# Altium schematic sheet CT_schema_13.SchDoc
size 254 x 194 mm
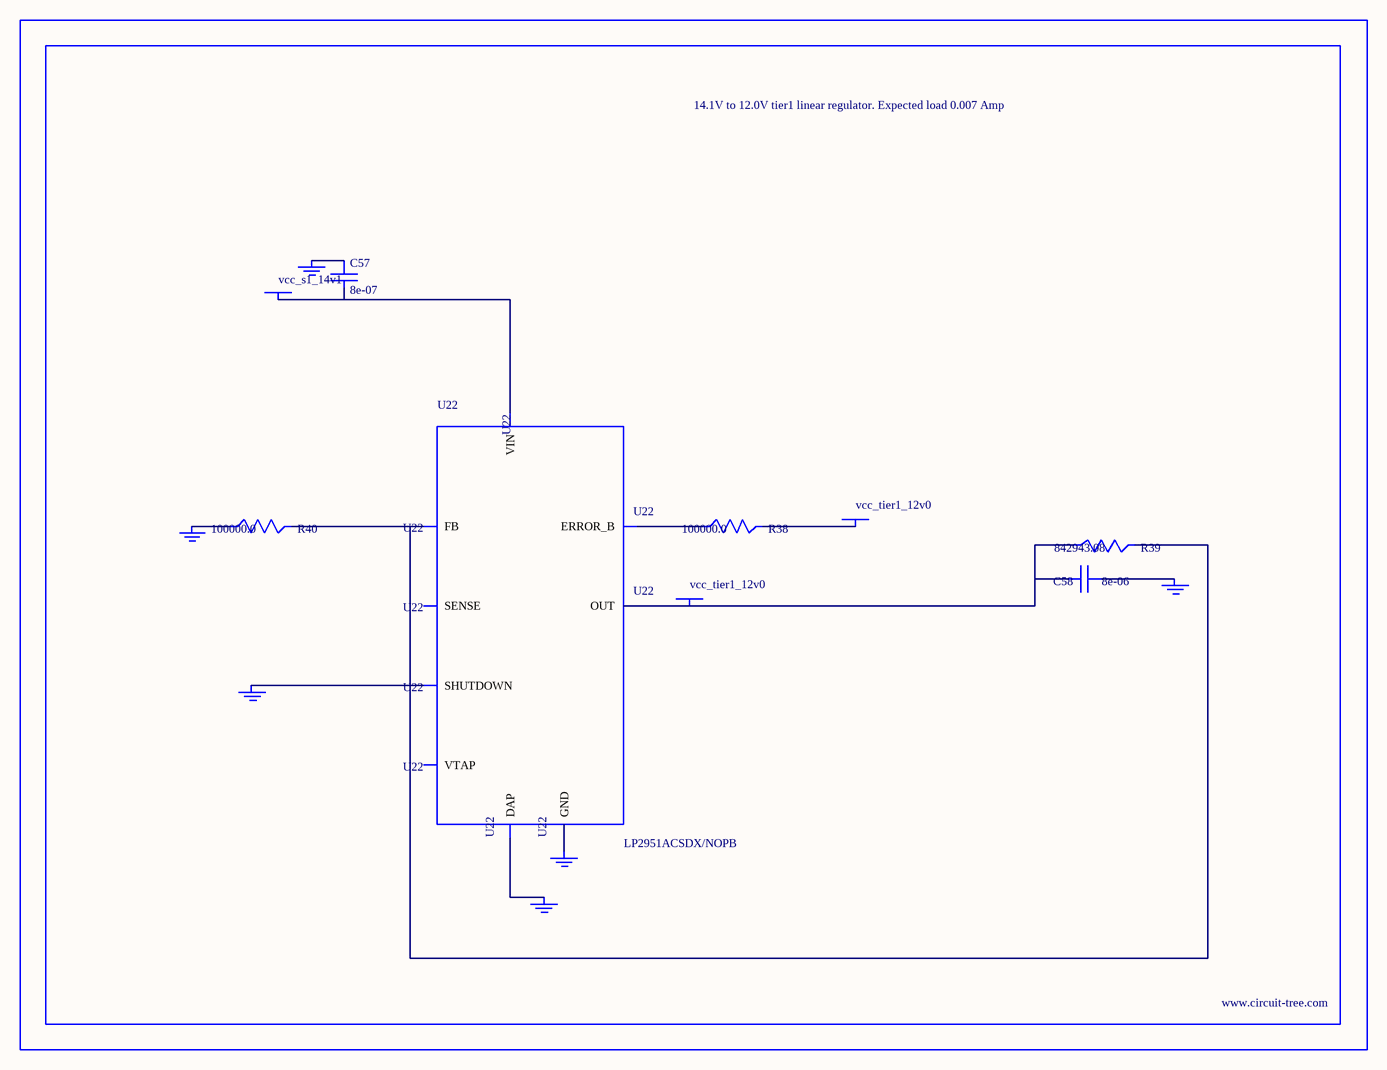
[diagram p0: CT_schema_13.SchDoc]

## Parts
BORDER12  (no value)
C57  8e-07  [R0603]
C58  8e-06  [R0603]
GND_INSTANCE_12_0  (no value)
GND_INSTANCE_12_1  (no value)
GND_INSTANCE_12_2  (no value)
GND_INSTANCE_12_3  (no value)
GND_INSTANCE_12_4  (no value)
GND_INSTANCE_12_5  (no value)
POWER_INSTANCE_12_0  vcc_tier1_12v0
POWER_INSTANCE_12_1  vcc_s1_14v1
POWER_INSTANCE_12_2  vcc_tier1_12v0
R38  100000.0  [R0603]
R39  842943.08  [R0603]
R40  100000.0  [R0603]
U22  LP2951ACSDX/NOPB  [WSON-8]

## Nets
NetC57_1: C57.1 GND_INSTANCE_12_3.0(GND)
NetC57_2: C57.2 POWER_INSTANCE_12_1.0(PWR) U22.8(VIN)
NetC58_1: C58.1 GND_INSTANCE_12_0.0(GND)
NetC58_2: C58.2 POWER_INSTANCE_12_2.0(PWR) R39.1 U22.1(OUT)
NetGND_INSTANCE_12_1_0: GND_INSTANCE_12_1.0(GND) U22.3(SHUTDOWN)
NetGND_INSTANCE_12_2_0: GND_INSTANCE_12_2.0(GND) R40.1
NetGND_INSTANCE_12_4_0: GND_INSTANCE_12_4.0(GND) U22.PAD(DAP)
NetGND_INSTANCE_12_5_0: GND_INSTANCE_12_5.0(GND) U22.4(GND)
NetPOWER_INSTANCE_12_0_0: POWER_INSTANCE_12_0.0(PWR) R38.2
NetR38_1: R38.1 U22.5(ERROR_B)
NetR39_2: R39.2 R40.2 U22.7(FB)

Not connected (* = marked no-connect by the designer): U22 2(SENSE) 6(VTAP)

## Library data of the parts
BORDER12 = BORDER_PAGE12
C57 = C57
C58 = C58
GND_INSTANCE_12_0-GND_INSTANCE_12_5 = GND
POWER_INSTANCE_12_0-POWER_INSTANCE_12_2 = PWR
R38 R40 = RC0603JR-07100KL
R39 = R39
